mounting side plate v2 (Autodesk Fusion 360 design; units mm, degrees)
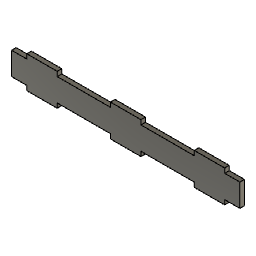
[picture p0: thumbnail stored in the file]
parameter "d6" = 3
sketch "Sketch1" plane through (0, 0, 0) normal (0, 1, 0) x axis (1, 0, 0)
  line L1 (150, 10.5) -> (0, 10.5)
  line L2 (150, -10.5) -> (150, 10.5)
  line L3 (0, -10.5) -> (150, -10.5)
  line L4 (0, 10.5) -> (0, -10.5)
  line L5 (150, 0) -> (0, 0)
  point P2 (0, 10.5)
  point P6 (0, 10.5)
  point P7 (0, 0)
  point P8 (150, 0)
  point P1 (0, 0)
  point P3 (150, 10.5)
  point P5 (0, -10.5)
  horizontal L1
  vertical L2
  horizontal L3
  vertical L4
  coincident P2 P6
  midpoint L4 P7
  perpendicular L4 L5
  midpoint L2 P8
  coincident P1 P7
  dimension "d1" distance P2 P3 = 150
  dimension "d2" distance P2 P5 = 21
extrude "Extrude1" new body sketch "Sketch1" profile of L1 L2 L3 L4 along normal blind 3
sketch "Sketch2" plane through (0, 0, 0) normal (0, -1, 0) x axis (1, 0, 0)
  line L1 (0, 10.5) -> (150, 10.5)
  line L2 (0, -10.5) -> (0, 10.5)
  line L3 (150, -10.5) -> (0, -10.5)
  line L4 (150, 10.5) -> (150, -10.5)
  line L5 (10, -7.5) -> (0, -7.5)
  line L6 (10, -10.5) -> (10, -7.5)
  line L7 (0, -10.5) -> (10, -10.5)
  line L8 (0, -7.5) -> (0, -10.5)
  line L9 (65, -7.5) -> (30, -7.5)
  line L10 (65, -10.5) -> (65, -7.5)
  line L11 (30, -10.5) -> (65, -10.5)
  line L12 (30, -7.5) -> (30, -10.5)
  line L13 (120, -7.5) -> (85, -7.5)
  line L14 (120, -10.5) -> (120, -7.5)
  line L15 (85, -10.5) -> (120, -10.5)
  line L16 (85, -7.5) -> (85, -10.5)
  line L17 (140, -10.5) -> (150, -10.5)
  line L18 (140, -7.5) -> (140, -10.5)
  line L19 (150, -7.5) -> (140, -7.5)
  line L20 (150, -10.5) -> (150, -7.5)
  point P8 (10, -10.5)
  point P6 (0, -7.5)
  point P12 (65, -10.5)
  point P16 (120, -10.5)
  point P5 (150, -10.5)
  point P18 (150, -10.5)
  point P7 (10, -7.5)
  point P13 (30, -10.5)
  point P21 (150, -7.5)
  point P20 (140, -7.5)
  horizontal L5
  vertical L6
  horizontal L7
  vertical L8
  coincident L3 P8
  coincident L2 P6
  horizontal L9
  vertical L10
  horizontal L11
  vertical L12
  coincident L3 P12
  horizontal L13
  vertical L14
  horizontal L15
  vertical L16
  coincident L3 P16
  horizontal L17
  vertical L18
  horizontal L19
  vertical L20
  coincident P5 P18
  dimension "d5" distance P6 P7 = 10
  dimension "d7" distance L6 L12 = 20
  dimension "d8" distance P12 P13 = 35
  dimension "d9" distance L9 L11 = 3
  dimension "d10" distance L10 L16 = 20
  dimension "d11" distance L13 L15 = 3
  dimension "d12" distance L14 L16 = 35
  dimension "d13" distance L14 L18 = 20
  dimension "d14" distance P18 P21 = 3
  dimension "d15" distance P20 P21 = 10
extrude "Extrude2" cut sketch "Sketch2" profile of L2 L3 L4 L5 L6 L7 L8 L9 L10 L11 L12 L13 L14 L15 L16 L17 L18 L19 L20 to an object
mirror "Mirror1"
